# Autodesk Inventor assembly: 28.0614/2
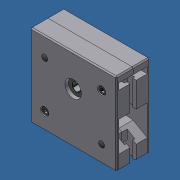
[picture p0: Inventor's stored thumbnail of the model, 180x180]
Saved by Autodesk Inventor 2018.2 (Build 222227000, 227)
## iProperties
Created: 2018-05
Part Number: 28.0614/2
Document SubType Name: Assembly
Designer: amoles
Description: TIMING BELT PULLEY T45 11mm
Stock Number: 28.0614 TIMING BELT PULLEY T45
Author: amoles
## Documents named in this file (12)
- Y:\INVENTOR LIBRARIES\PARTS LIBRARY\READY FOR USE MODULES LR\28.0614_2 TIMING BELT PULLEY T45 11mm.iam
- Y:\INVENTOR LIBRARIES\PARTS LIBRARY\READY FOR USE MODULES LR\SUBCOMPONENTS\28.0614 TIMING BELT PULLEY T45 RIGHT PLATE.ipt
- Y:\INVENTOR LIBRARIES\PARTS LIBRARY\READY FOR USE MODULES LR\SUBCOMPONENTS\SHIM DIN 988 - 25 x 35 x 0,1.ipt
- 00005263.ipt
- Y:\INVENTOR LIBRARIES\PARTS LIBRARY\READY FOR USE MODULES LR\Subcomponents\28.0083 BEARING.ipt
- Y:\INVENTOR LIBRARIES\PARTS LIBRARY\READY FOR USE MODULES LR\SUBCOMPONENTS\SHIM DIN 988 - 37 x 47 x 0,1.ipt
- 00005262.ipt
- Y:\INVENTOR LIBRARIES\PARTS LIBRARY\READY FOR USE MODULES LR\SUBCOMPONENTS\28.0614 TIMING BELT PULLEY T45 LEFT PLATE.ipt
- Y:\INVENTOR LIBRARIES\PARTS LIBRARY\FASTENING ELEMENTS\SCREWS CAP\M6X30 HIGH HEAD.ipt
- 00005264.ipt
- Y:\INVENTOR LIBRARIES\PARTS LIBRARY\END CAPS\22.1203 HOLE CAP M6.ipt
- Y:\INVENTOR LIBRARIES\PARTS LIBRARY\READY FOR USE MODULES LR\SUBCOMPONENTS\28.0047_1 T45 PULLEY 11mm.ipt
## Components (17 placed, 8 different names)
1. 28.0614 TIMING BELT PULLEY T45 RIGHT PLATE:1 — Flush:1, Flush:2, Flush:3, Mate:5, Mate:6, Mate:7, Angle:1, Insert:7, Insert:8, Insert:11, Insert:12, Angle:2
2. 28.0047/1 T45 PULLEY 11mm:1 — Insert:1, Insert:2, Mate:1, Mate:3, Mate:5, Mate:6, Mate:8, Angle:2
3. 00005263:1 — Insert:1, Insert:3
4. 00005263:2 — Insert:2, Insert:4
5. 28.0083 BEARING:1 — Insert:4, Mate:4
6. 28.0083 BEARING:2 — Insert:3, Mate:2
7. 00005262:1 — Mate:1, Mate:2
8. 00005262:2 — Mate:3, Mate:4
9. 28.0614 TIMING BELT PULLEY T45 LEFT PLATE:1 — Mate:7, Mate:8, Angle:1, Insert:5, Insert:6, Insert:9, Insert:10
10. 00005264:1 — Insert:6
11. 00005264:2 — Insert:5
12. 00005264:3 — Insert:8
13. 00005264:4 — Insert:7
14. 22.1203 HOLE CAP M6:1 — Insert:9
15. 22.1203 HOLE CAP M6:2 — Insert:10
16. 22.1203 HOLE CAP M6:3 — Insert:12
17. 22.1203 HOLE CAP M6:4 — Insert:11
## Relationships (25: Insert 12, Mate 8, Flush 3, Angle 2)
- Flush:1: 28.0614 TIMING BELT PULLEY T45 RIGHT PLATE:1
- Flush:2: 28.0614 TIMING BELT PULLEY T45 RIGHT PLATE:1
- Flush:3: 28.0614 TIMING BELT PULLEY T45 RIGHT PLATE:1
- Insert:1: 28.0047/1 T45 PULLEY 11mm:1 ↔ 00005263:1
- Insert:2: 28.0047/1 T45 PULLEY 11mm:1 ↔ 00005263:2
- Insert:3: 00005263:1 ↔ 28.0083 BEARING:2
- Insert:4: 00005263:2 ↔ 28.0083 BEARING:1
- Mate:1: 28.0047/1 T45 PULLEY 11mm:1 ↔ 00005262:1
- Mate:2: 28.0083 BEARING:2 ↔ 00005262:1
- Mate:3: 28.0047/1 T45 PULLEY 11mm:1 ↔ 00005262:2
- Mate:4: 28.0083 BEARING:1 ↔ 00005262:2
- Mate:5: 28.0614 TIMING BELT PULLEY T45 RIGHT PLATE:1 ↔ 28.0047/1 T45 PULLEY 11mm:1
- Mate:6: 28.0614 TIMING BELT PULLEY T45 RIGHT PLATE:1 ↔ 28.0047/1 T45 PULLEY 11mm:1
- Mate:7: 28.0614 TIMING BELT PULLEY T45 RIGHT PLATE:1 ↔ 28.0614 TIMING BELT PULLEY T45 LEFT PLATE:1
- Mate:8: 28.0047/1 T45 PULLEY 11mm:1 ↔ 28.0614 TIMING BELT PULLEY T45 LEFT PLATE:1
- Angle:1: 28.0614 TIMING BELT PULLEY T45 RIGHT PLATE:1 ↔ 28.0614 TIMING BELT PULLEY T45 LEFT PLATE:1
- Insert:5: 28.0614 TIMING BELT PULLEY T45 LEFT PLATE:1 ↔ 00005264:2
- Insert:6: 28.0614 TIMING BELT PULLEY T45 LEFT PLATE:1 ↔ 00005264:1
- Insert:7: 28.0614 TIMING BELT PULLEY T45 RIGHT PLATE:1 ↔ 00005264:4
- Insert:8: 28.0614 TIMING BELT PULLEY T45 RIGHT PLATE:1 ↔ 00005264:3
- Insert:9: 28.0614 TIMING BELT PULLEY T45 LEFT PLATE:1 ↔ 22.1203 HOLE CAP M6:1
- Insert:10: 28.0614 TIMING BELT PULLEY T45 LEFT PLATE:1 ↔ 22.1203 HOLE CAP M6:2
- Insert:11: 28.0614 TIMING BELT PULLEY T45 RIGHT PLATE:1 ↔ 22.1203 HOLE CAP M6:4
- Insert:12: 28.0614 TIMING BELT PULLEY T45 RIGHT PLATE:1 ↔ 22.1203 HOLE CAP M6:3
- Angle:2: 28.0614 TIMING BELT PULLEY T45 RIGHT PLATE:1 ↔ 28.0047/1 T45 PULLEY 11mm:1
